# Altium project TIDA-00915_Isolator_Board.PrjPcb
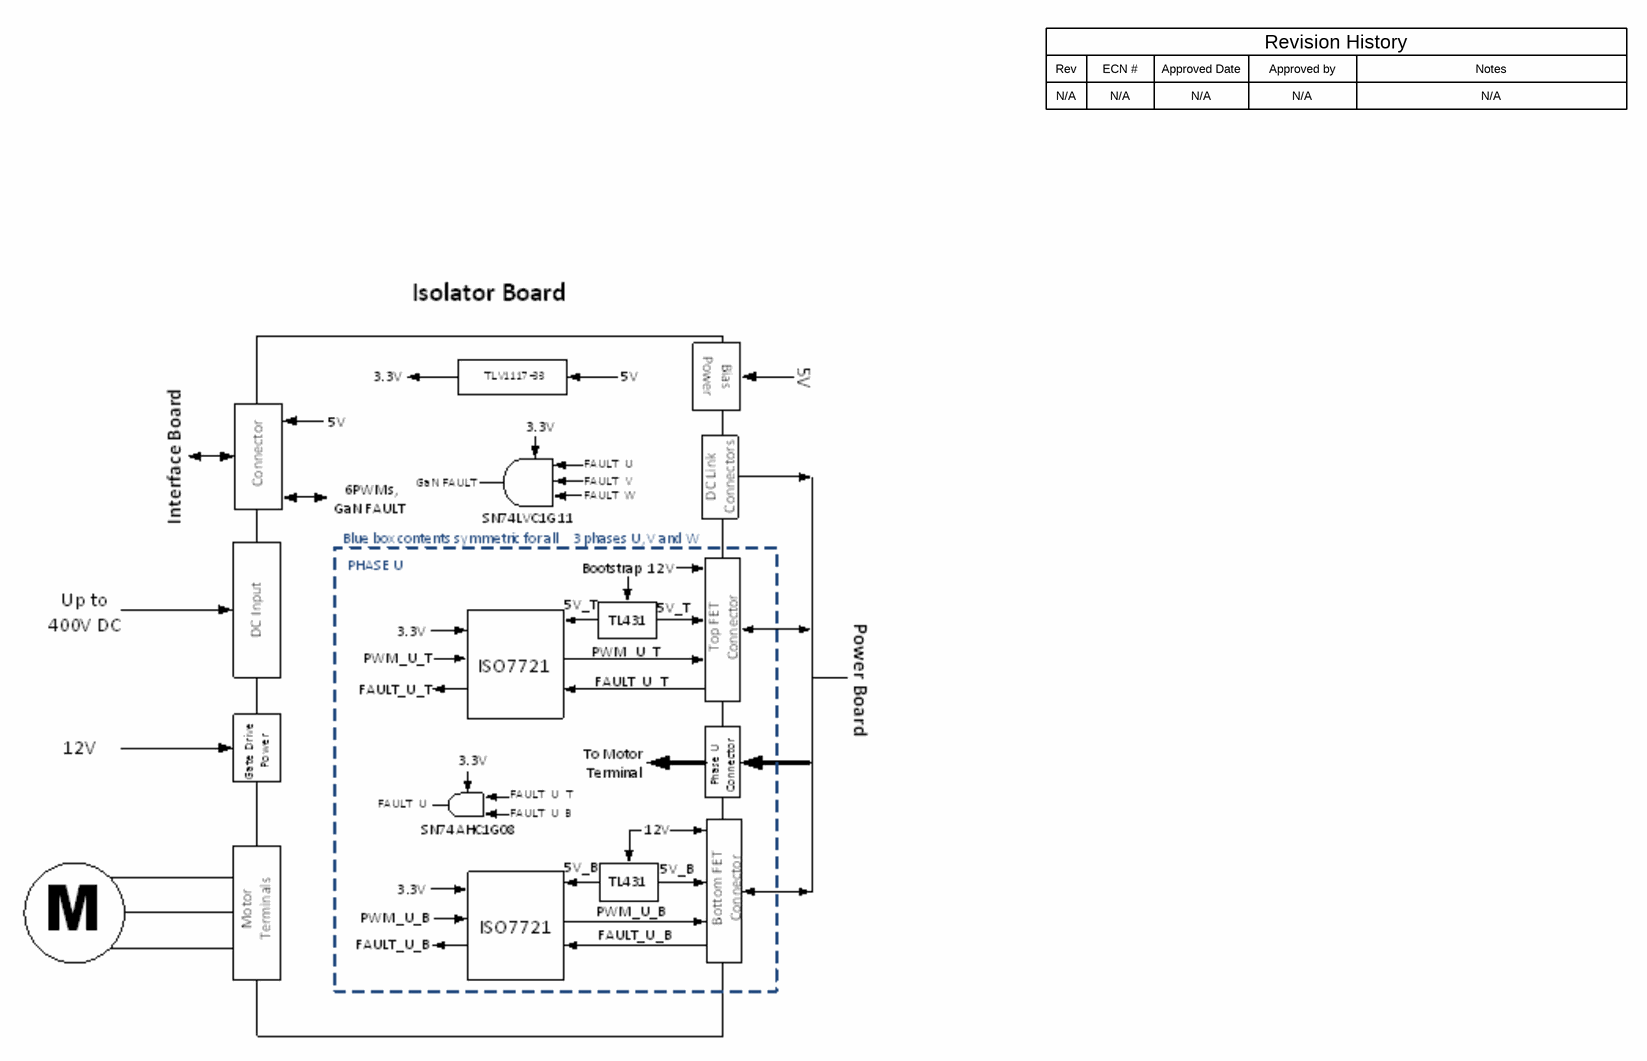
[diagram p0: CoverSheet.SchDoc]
TID: 00915; TechSupport: http://www.ti.com/support; SCH_Rev: E1; PRJ_Title: TIDA-00915_Isolator_Board; PRJ_Number: TIDA-00915_Isolator_Board; PRJ_Customer: Public Release; PCB_Rev: E1; CopyrightYear: 2019
6 sheets, 132 parts. Net scope: global (net labels, ports and power ports of the same name join across sheets).
Board file: TIDA-00915_Isolator_Board.PcbDoc
Sheets:
  CoverSheet.SchDoc
  EVM_Hardware.SchDoc
  Phase_U.SchDoc
  Phase_V.SchDoc
  Phase_W.SchDoc
  MCU_Interface.SchDoc

## Sheet CoverSheet.SchDoc
size 431 x 279 mm; Date: Not shown in title block; ApprovedBy: Not shown in title block; CheckedBy: Not shown in title block; Author: Not shown in title block; CompanyName: Not shown in title block; Engineer: Not shown in title block; Organization: Not shown in title block; Address1: Not shown in title block; Address2: Not shown in title block; Address3: Not shown in title block; Address4: Not shown in title block; DocumentNumber: 1; Revision: Use project parameter SCH_Rev; SheetNumber: 1; SheetTotal: 3; PageSetup: Record=PageOptions¦CenterHorizontal=True¦CenterVertical=True¦PrintScale=1.00¦XCorrection=1.00¦YCorrection=1.00¦PrintKind=0¦BorderSize=5000000¦LeftOffset=0¦BottomOffset=0¦Orientation=2¦PaperLength=1000¦PaperWidth=1000¦Scale=100¦PaperSource=15¦PrintQuality=600¦MediaType=1¦DitherType=10¦PaperKind=Letter¦PrintScaleMode=1

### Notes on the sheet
- Rev
- N/A
- ECN #
- Approved Date
- Approved by
- Revision History
- Notes

## Sheet EVM_Hardware.SchDoc
size 431 x 279 mm; Date: Not shown in title block; ApprovedBy: Not shown in title block; CheckedBy: Not shown in title block; Author: Not shown in title block; CompanyName: Not shown in title block; Engineer: Not shown in title block; Organization: Not shown in title block; Address1: Not shown in title block; Address2: Not shown in title block; Address3: Not shown in title block; Address4: Not shown in title block; DocumentNumber: 1; Revision: Use project parameter SCH_Rev; SheetNumber: 3; SheetTotal: 3; PageSetup: Record=PageOptions¦CenterHorizontal=True¦CenterVertical=True¦PrintScale=1.00¦XCorrection=1.00¦YCorrection=1.00¦PrintKind=0¦BorderSize=5000000¦LeftOffset=0¦BottomOffset=0¦Orientation=2¦PaperLength=1000¦PaperWidth=1000¦Scale=100¦PaperSource=15¦PrintQuality=600¦MediaType=1¦DitherType=10¦PaperKind=Letter¦PrintScaleMode=1
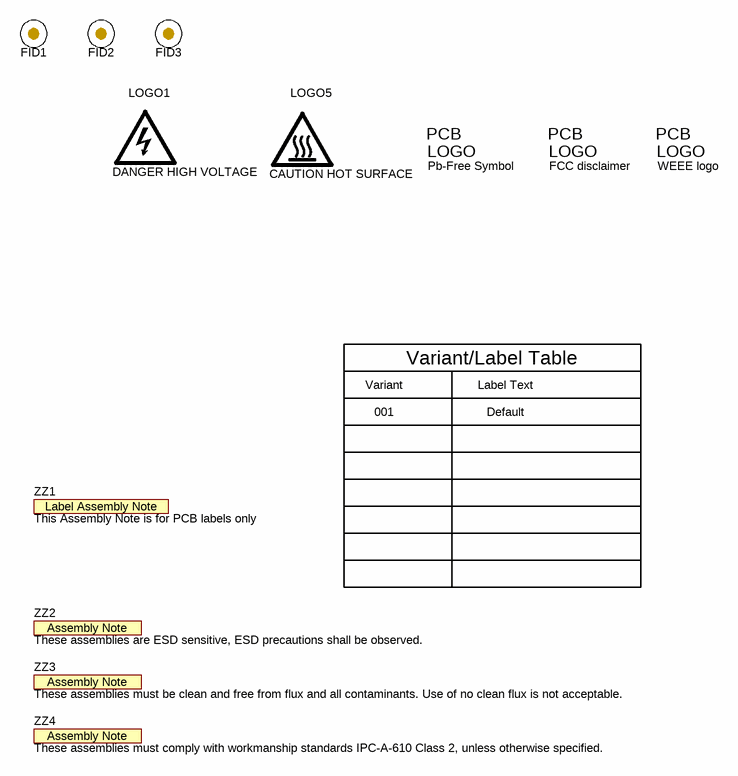
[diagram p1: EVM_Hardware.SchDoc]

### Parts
FID1  Fiducial  [Fiducial10-20]  (value not drawn)
FID2  Fiducial  [Fiducial10-20]  (value not drawn)
FID3  Fiducial  [Fiducial10-20]  (value not drawn)
LOGO1  DANGER HIGH VOLTAGE  [IEC_HighVoltage_Small]  (no BOM)
Logo2  Pb-Free Symbol  [Pb-Free_Overlay_Small]  (no BOM)
Logo3  FCC disclaimer  [FCC_disclaimer]  (no BOM)
Logo4  WEEE logo  [WEEE_Minimum]  (no BOM)
LOGO5  CAUTION HOT SURFACE  [IEC_HotSurface_Small]  (no BOM)
ZZ1  This Assembly Note is for PCB labels only  [AssemblyNoteLabel]  (no BOM)
ZZ2  These assemblies are ESD sensitive, ESD precautions shall be observed.  [AssemblyNote]  (no BOM)
ZZ3  These assemblies must be clean and free from flux and all contaminants. Use of no clean flux is not acceptable.  [AssemblyNote]  (no BOM)
ZZ4  These assemblies must comply with workmanship standards IPC-A-610 Class 2, unless otherwise specified.  [AssemblyNote]  (no BOM)

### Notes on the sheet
- Variant
- Variant/Label Table
- Label Text
- 001
- Default

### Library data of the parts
FID1-FID3 = CMP-0077181-1: Fiducial mark.  There is nothing to buy or mount.
LOGO1 = CMP-0074835-1: IEC 61010-1 High Voltage Warning; Library Reference: IEC_HighVoltage; SymbolCreator: a0412235
Logo2 = CMP-0074839-1: SymbolCreator: a0412235; Library Reference: Logo
Logo3 = CMP-0074847-1: FCC_disclaimer; Library Reference: Logo
Logo4 = CMP-0074769-1
LOGO5 = CMP-0074837-1: IEC 61010-1 Hot Surface Warning; Library Reference: IEC_HotSurface; SymbolCreator: a0412235
ZZ1 = CMP-0003616-3
ZZ2 = CMP-0077236-1
ZZ3 = CMP-0077237-1
ZZ4 = CMP-0077238-1

## Sheet Phase_U.SchDoc
size 431 x 279 mm; Date: Not shown in title block; ApprovedBy: Not shown in title block; CheckedBy: Not shown in title block; Author: Not shown in title block; CompanyName: Not shown in title block; Engineer: Not shown in title block; Organization: Not shown in title block; Address1: Not shown in title block; Address2: Not shown in title block; Address3: Not shown in title block; Address4: Not shown in title block; DocumentNumber: 1; Revision: Use project parameter SCH_Rev; SheetNumber: 2; SheetTotal: 3; PageSetup: Record=PageOptions¦CenterHorizontal=True¦CenterVertical=True¦PrintScale=1.00¦XCorrection=1.00¦YCorrection=1.00¦PrintKind=0¦BorderSize=5000000¦LeftOffset=0¦BottomOffset=0¦Orientation=2¦PaperLength=1000¦PaperWidth=1000¦Scale=100¦PaperSource=15¦PrintQuality=600¦MediaType=1¦DitherType=10¦PaperKind=Letter¦PrintScaleMode=1
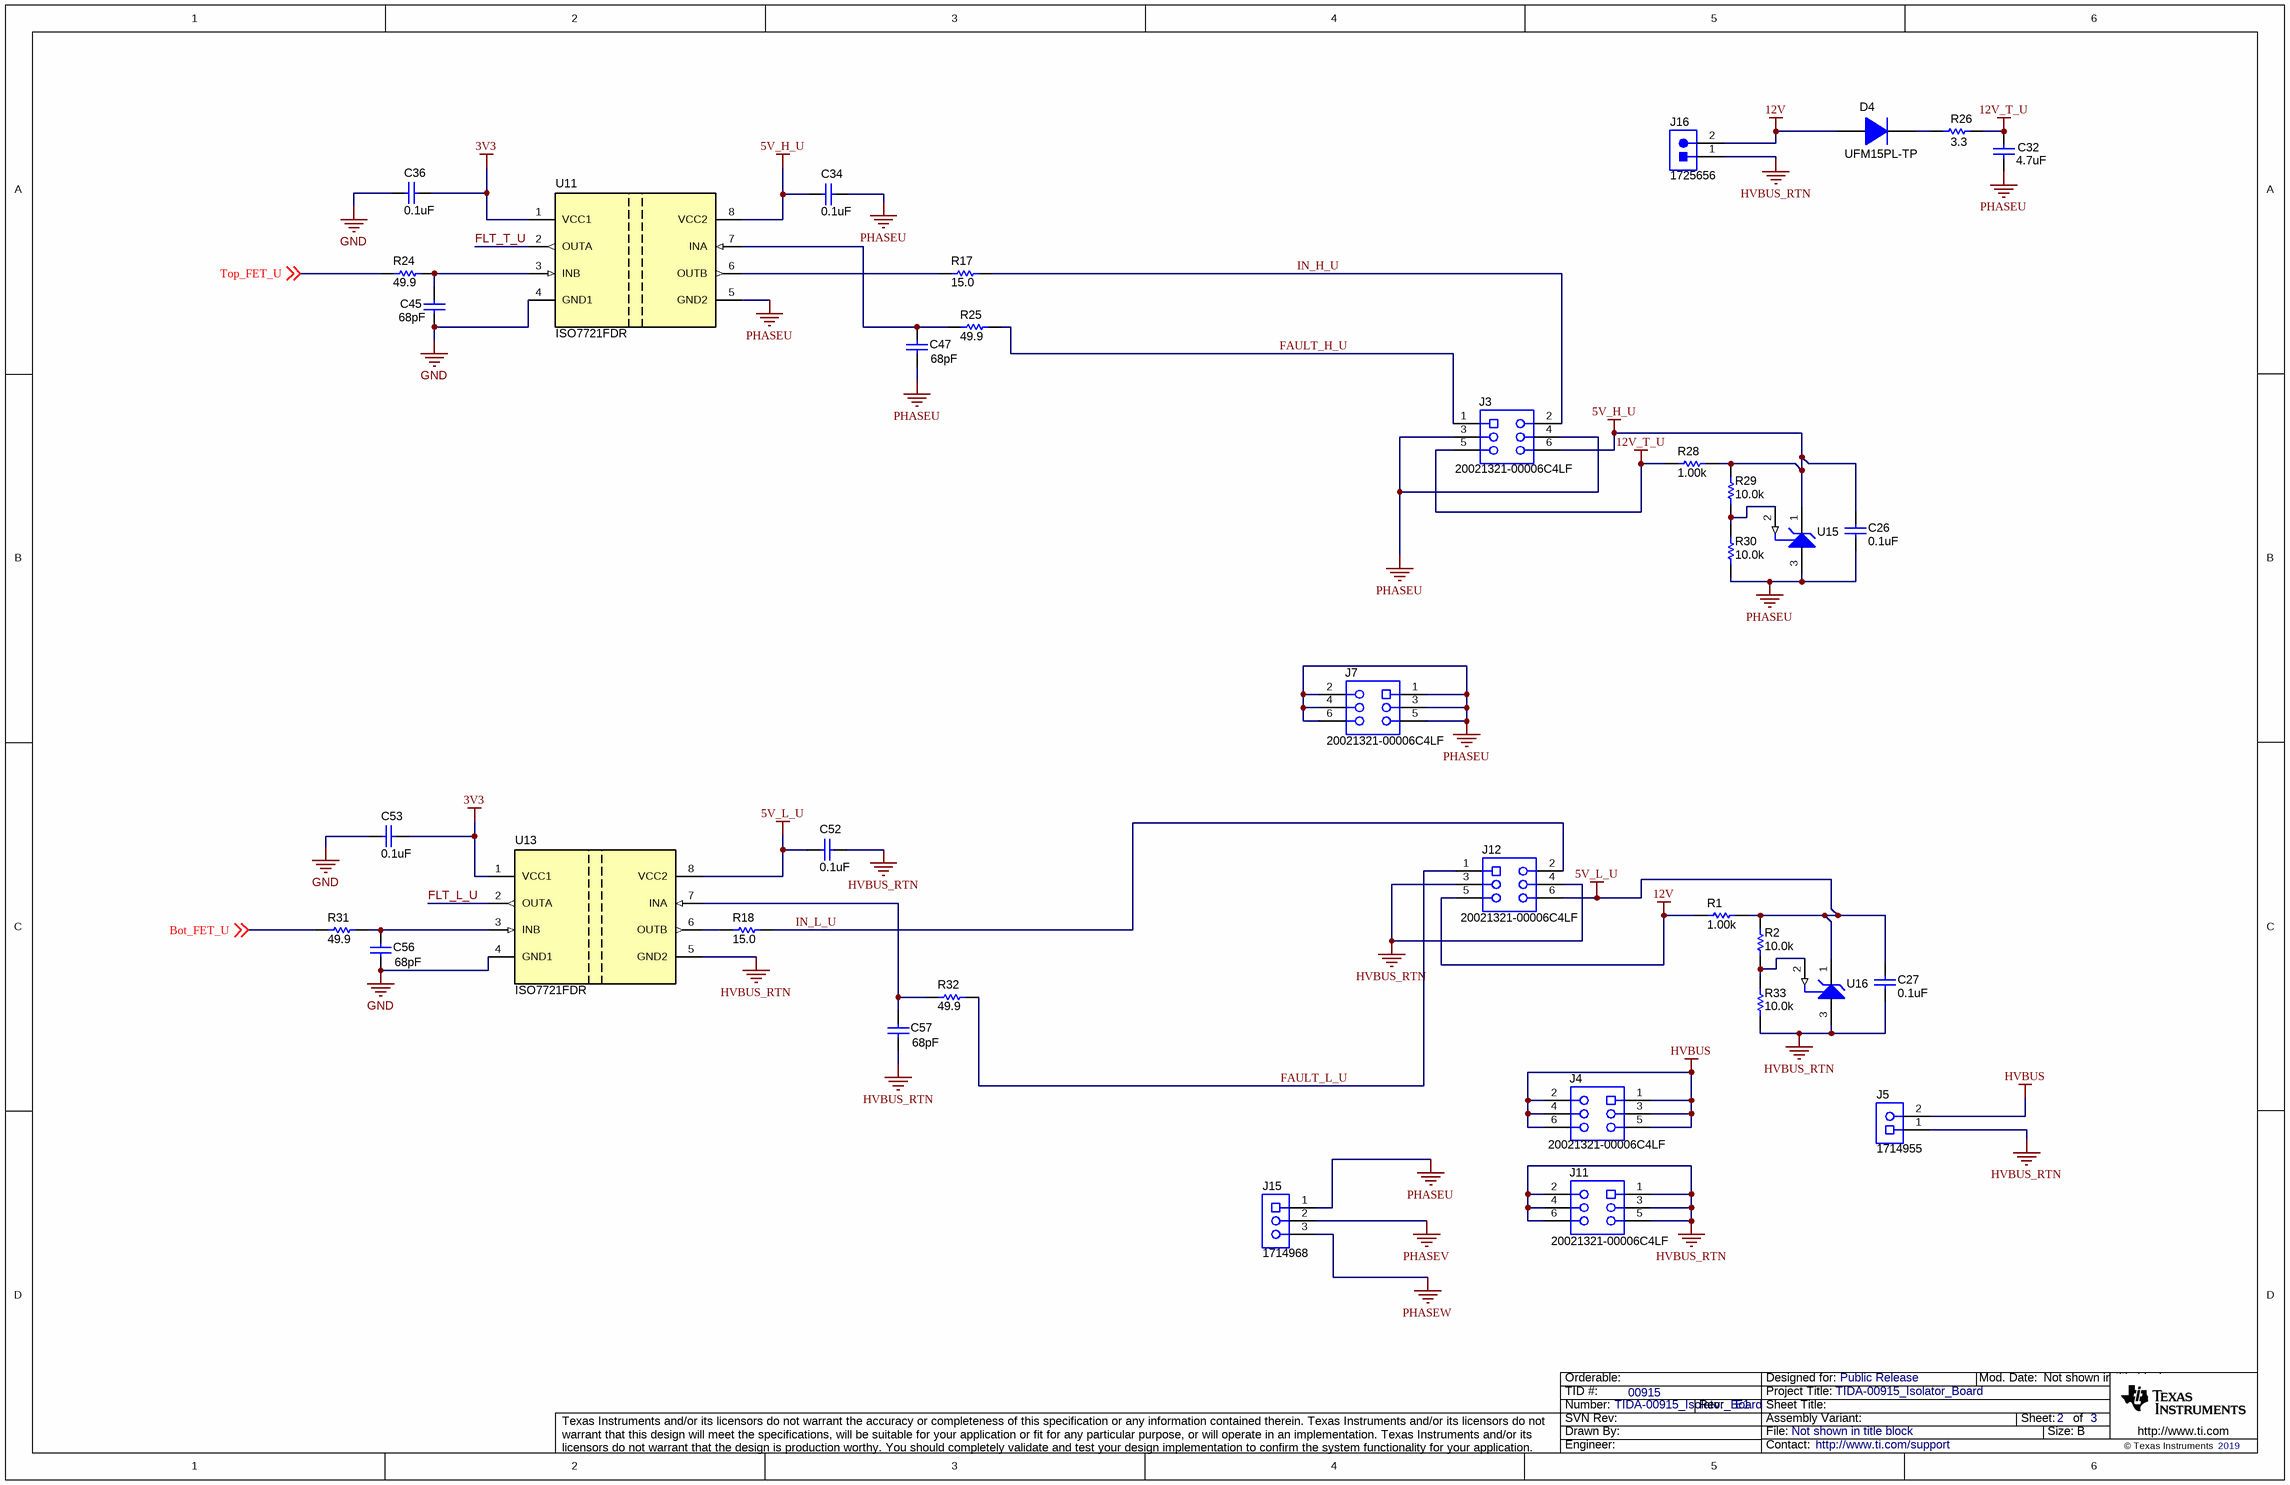
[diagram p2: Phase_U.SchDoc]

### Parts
C26  ValueDisplayed: 0.1uF  [0603]  (hidden comment: 06035C104KAT2A)
C27  ValueDisplayed: 0.1uF  [0603]  (hidden comment: 06035C104KAT2A)
C32  ValueDisplayed: 4.7uF  [0805_HV]  (hidden comment: C2012X7R1V475K125AC)
C34  ValueDisplayed: 0.1uF  [0603]  (hidden comment: 06035C104KAT2A)
C36  ValueDisplayed: 0.1uF  [0603]  (hidden comment: 06035C104KAT2A)
C45  ValueDisplayed: 68pF  [0402]  (hidden comment: C1005C0G1H680J050BA)
C47  ValueDisplayed: 68pF  [0402]  (hidden comment: C1005C0G1H680J050BA)
C52  ValueDisplayed: 0.1uF  [0603]  (hidden comment: 06035C104KAT2A)
C53  ValueDisplayed: 0.1uF  [0603]  (hidden comment: 06035C104KAT2A)
C56  ValueDisplayed: 68pF  [0402]  (hidden comment: C1005C0G1H680J050BA)
C57  ValueDisplayed: 68pF  [0402]  (hidden comment: C1005C0G1H680J050BA)
D4  UFM15PL-TP  [SOD-123FL]
J3  20021321-00006C4LF  [FCI_20021321-00006XXLF]
J4  20021321-00006C4LF  [FCI_20021321-00006XXLF]
J5  1714955  [Phoenix_1714955]
J7  20021321-00006C4LF  [FCI_20021321-00006XXLF]
J11  20021321-00006C4LF  [FCI_20021321-00006XXLF]
J12  20021321-00006C4LF  [FCI_20021321-00006XXLF]
J15  1714968  [Phoenix_1714968]
J16  1725656  [CONN_1725656_1]
R1  ValueDisplayed: 1.00k  [0603]  (hidden comment: RC0603FR-071KL)
R2  ValueDisplayed: 10.0k  [0402]  (hidden comment: RC0402FR-0710KL)
R17  ValueDisplayed: 15.0  [0603]  (hidden comment: RC0603FR-0715RL)
R18  ValueDisplayed: 15.0  [0603]  (hidden comment: RC0603FR-0715RL)
R24  ValueDisplayed: 49.9  [0603]  (hidden comment: RC0603FR-0749R9L)
R25  ValueDisplayed: 49.9  [0603]  (hidden comment: RC0603FR-0749R9L)
R26  ValueDisplayed: 3.3  [0603]  (hidden comment: CRCW06033R30JNEA)
R28  ValueDisplayed: 1.00k  [0603]  (hidden comment: RC0603FR-071KL)
R29  ValueDisplayed: 10.0k  [0402]  (hidden comment: RC0402FR-0710KL)
R30  ValueDisplayed: 10.0k  [0402]  (hidden comment: RC0402FR-0710KL)
R31  ValueDisplayed: 49.9  [0603]  (hidden comment: RC0603FR-0749R9L)
R32  ValueDisplayed: 49.9  [0603]  (hidden comment: RC0603FR-0749R9L)
R33  ValueDisplayed: 10.0k  [0402]  (hidden comment: RC0402FR-0710KL)
U11  ISO7721FDR  [D0008B_HV]
U13  ISO7721FDR  [D0008B_HV]
U15  TL431ACDBZT  [DBZ0003A_N]  (value not drawn)
U16  TL431ACDBZT  [DBZ0003A_N]  (value not drawn)

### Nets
3V3: C36.2 C53.2 U11.1(VCC1) U13.1(VCC1)
5V_H_U: C26.1 C34.1 J3.6 R28.2 R29.2 U11.8(VCC2) U15.1(CATHODE)
5V_L_U: C27.1 C52.1 J12.6 R1.2 R2.2 U13.8(VCC2) U16.1(CATHODE)
12V: D4.2(A) J12.5 J16.2 R1.1
12V_T_U: C32.1 J3.5 R26.2 R28.1
GND: C36.1 C45.2 C53.1 C56.2 U11.4(GND1) U13.4(GND1)
HVBUS: J4.1 J4.2 J4.3 J4.4 J4.5 J4.6 J5.2
HVBUS_RTN: C27.2 C52.2 C57.2 J5.1 J11.1 J11.2 J11.3 J11.4 J11.5 J11.6 J12.3 J12.4 J16.1 R33.1 U13.5(GND2) U16.3(ANODE)
PHASEU: C26.2 C32.2 C34.2 C47.2 J3.3 J3.4 J7.1 J7.2 J7.3 J7.4 J7.5 J7.6 J15.1 R30.1 U11.5(GND2) U15.3(ANODE)
PHASEV: J15.2
PHASEW: J15.3
Bot_FET_U: R31.1 ; off-sheet Bot_FET_U
FAULT_H_U: J3.1 R25.2
FAULT_L_U: J12.1 R32.2
FLT_L_U: U13.2(OUTA)
FLT_T_U: U11.2(OUTA)
IN_H_U: J3.2 R17.2
IN_L_U: J12.2 R18.2
Top_FET_U: R24.1 ; off-sheet Top_FET_U
NetC45_1: C45.1 R24.2 U11.3(INB)
NetC47_1: C47.1 R25.1 U11.7(INA)
NetC56_1: C56.1 R31.2 U13.3(INB)
NetC57_1: C57.1 R32.1 U13.7(INA)
NetD4_1: D4.1(K) R26.1
NetR2_1: R2.1 R33.2 U16.2(REF)
NetR17_1: R17.1 U11.6(OUTB)
NetR18_1: R18.1 U13.6(OUTB)
NetR29_1: R29.1 R30.2 U15.2(REF)

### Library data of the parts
C26 C27 C34 C36 C52 C53 = CMP-0006802-4: CAP, CERM, 0.1 uF, 50 V, +/- 10%, X7R, 0603; Manufacturer: AVX; TaMin_C: -55°C; Polarized: N; SizeAreaWB_mm2: 4.68; Value1: Unknown; U/M: EA; Value: 0.1uF; TaMax_C: 125°C; SizeZ_mm: 1; SizeX_mm: 1.6; SizeY_mm: 0.8; Value2: 50V; SizeArea_mm2: 1.28; CompType: Capacitor; Cap_F: 100nF; AEC Category: Q200
C32 = CMP-0007885-2: CAP, CERM, 4.7 uF, 35 V, +/- 10%, X7R, 0805; Manufacturer: TDK; TaMin_C: -55°C; ESR_ohm: 2.346m; Polarized: N; SizeAreaWB_mm2: 6.75; Value1: 0.002346 ohm; U/M: EA; Value: 4.7uF; TaMax_C: 125°C; SizeZ_mm: 1.45; SizeX_mm: 2; SizeY_mm: 1.25; Cap_Case: 0805; Value2: 35V; SizeArea_mm2: 2.5; CompType: Capacitor; Cap_F: 4.7µF; IRMS_A: 4.26021A; AEC Category: Q200
C45 C47 C56 C57 = CMP-0006251-2: CAP, CERM, 68 pF, 50 V, +/- 5%, C0G/NP0, 0402; Manufacturer: TDK; TaMin_C: -55°C; Polarized: N; SizeAreaWB_mm2: 3; Value1: Unknown; U/M: EA; Value: 68pF; TaMax_C: 125°C; SizeZ_mm: 0.6; SizeX_mm: 1; SizeY_mm: 0.5; Value2: 50V; CompType: Capacitor; AEC Category: Q200
D4 = CMP-0029148-2: Diode, Ultrafast, 600 V, 1 A, SOD-123FL; Manufacturer: Micro Commercial Components; SizeY_mm: 1.65; Value: 600V; Io_A: 1A; Green_Lifecycle: Not Set; Green_REACh: Incomplete; SizeX_mm: 3.6; SizeAreaWB_mm2: 12.19; SizeArea_mm2: 5.94; AEC Qualified: N; Value2: 1.7V; SizeZ_mm: 0.98; AEC Category: Q101; TJmax_C: 150°C
J3 J4 J7 J11 J12 = CMP-0086011-1: Receptacle, 1.27mm, 3x2, Gold, SMT; Manufacturer: FCI; Row_Count: 2; Gender: Female; RowSpacing_mm: 1.27
J5 = CMP-0055505-1: Terminal Block, 2x1, 6.35mm, Green, TH; Manufacturer: Phoenix Contact; CNHeader: FALSE; Shrouded: Y; Gender: Female; Row_Count: 1; Pitch_mm: 6.35; CT: TRUE
J15 = CMP-0055483-1: Terminal Block, 3x1, 6.35 mm, TH; Manufacturer: Phoenix Contact; CT: TRUE; CNHeader: FALSE
J16 = CMP-0055479-2: Terminal Block, 100mil, 2x1, 6A, 63V, TH; Manufacturer: Phoenix Contact; Green_REACh: Incomplete; CNHeader: FALSE; CT: TRUE; Green_Lifecycle: Not Set
R1 R28 = CMP-0022895-5: RES, 1.00 k, 1%, 0.1 W, 0603; Manufacturer: Yageo; Power_W: 100mW; TempCo: 100 ppm/C; Value_Code: 1k00; Value: 1.00k; EIA_Code: E96; Res_ohm: 1k; SizeX_mm: 1.6; SizeY_mm: 0.8; SizeZ_mm: 1; Value2: 0.1W; SizeArea_mm2: 1.28; CompType: Resistor; AEC Qualified: N; VDC_V: 75V; AEC Category: Q200; SizeAreaWB_mm2: 4.68
R2 R33 = CMP-0078669-1: RES, 10.0 k, 1%, 0.063 W, 0402; Manufacturer: Yageo America; Power_W: 63mW; Green_Lifecycle: Active; TempCo: 100 ppm/C; Value_Code: 10k0; Green_REACh: Passed; Value: 10.0k; EIA_Code: E96; Res_ohm: 10k; SizeX_mm: 1; SizeY_mm: 0.5; SizeZ_mm: 0.6; Value2: 0.063W; CompType: Resistor; AEC Qualified: N; AEC Category: Q200
R17 R18 = CMP-0022819-4: RES, 15.0, 1%, 0.1 W, 0603; Manufacturer: Yageo; Power_W: 100mW; TempCo: 100 ppm/C; Value_Code: 15R0; Value: 15.0; EIA_Code: E96; Res_ohm: 15; SizeX_mm: 1.6; SizeY_mm: 0.8; SizeZ_mm: 1; Value2: 0.1W; SizeArea_mm2: 1.28; AEC Qualified: N; VDC_V: 75V; AEC Category: Q200; SizeAreaWB_mm2: 4.68
R24 R25 R31 R32 = CMP-0023143-5: RES, 49.9, 1%, 0.1 W, 0603; Manufacturer: Yageo; Power_W: 100mW; TempCo: 100 ppm/C; Value_Code: 49R9; Value: 49.9; EIA_Code: E96; SizeX_mm: 1.6; SizeY_mm: 0.8; SizeZ_mm: 1; Value2: 0.1W; SizeArea_mm2: 1.28; AEC Qualified: N; VDC_V: 75V; AEC Category: Q200; SizeAreaWB_mm2: 4.68
R26 = CMP-0025805-4: RES, 3.3, 5%, 0.1 W, AEC-Q200 Grade 0, 0603; Manufacturer: Vishay-Dale; Power_W: 100mW; TempCo: 200 ppm/C; Value_Code: 3R30; Value: 3.3; EIA_Code: E24; SizeX_mm: 1.6; SizeY_mm: 0.8; SizeZ_mm: 1; Value2: 0.1W; SizeArea_mm2: 1.28; CompType: Resistor; AEC Qualified: Y; VDC_V: 75V; AEC Category: Q200; AEC Grade: 0
R29 R30 = CMP-0078669-1: RES, 10.0 k, 1%, 0.063 W, 0402; Manufacturer: Yageo America; Power_W: 63mW; Green_Lifecycle: Active; TempCo: 100 ppm/C; Value_Code: 10k0; Green_REACh: Passed; Value: 10.0k; EIA_Code: E96; Res_ohm: 10k; SizeX_mm: 1; SizeY_mm: 0.5; SizeZ_mm: 0.6; Value2: 0.063W; AEC Qualified: N; AEC Category: Q200
U11 U13 = CMP-0085673-1: High Speed, Robust EMC Reinforced Dual-Channel Digital Isolator, D0008B (SOIC-8); Alternate Manufacturer: Texas Instruments; Rating: Catalog; SizeAreaWB_mm2: 55.2; SizeY_mm: 4.9; SizeZ_mm: 1.75; AEC Qualified: N; SizeX_mm: 6; CompType: IC; SizeArea_mm2: 29.4; AEC Category: Q200
U15 U16 = CMP-0033071-1: Adjustable Precision Shunt Regulator, 34 ppm / degC, 100 mA, 0 to 70 degC, 3-pin SOT-23 (DBZ), Green (RoHS & no Sb/Br); Manufacturer: Texas Instruments; VO Adj(Max)(V): 36; Iout/Iz(Max)(mA): 100; Min Iz for Regulation(uA): 600; Temp Coeff(Typ)(ppm/ degree C): 34; SubFamily: Shunt Voltage Reference; Initial Accuracy @ 25/deg C(%): 1; Temp Coeff(Max)(ppm/ degree C): 92; Rating: Catalog; VO Adj(Min)(V): 2.495

## Sheet Phase_V.SchDoc
size 431 x 279 mm; Date: Not shown in title block; ApprovedBy: Not shown in title block; CheckedBy: Not shown in title block; Author: Not shown in title block; CompanyName: Not shown in title block; Engineer: Not shown in title block; Organization: Not shown in title block; Address1: Not shown in title block; Address2: Not shown in title block; Address3: Not shown in title block; Address4: Not shown in title block; DocumentNumber: 1; Revision: Use project parameter SCH_Rev; SheetNumber: 2; SheetTotal: 3; PageSetup: Record=PageOptions¦CenterHorizontal=True¦CenterVertical=True¦PrintScale=1.00¦XCorrection=1.00¦YCorrection=1.00¦PrintKind=0¦BorderSize=5000000¦LeftOffset=0¦BottomOffset=0¦Orientation=2¦PaperLength=1000¦PaperWidth=1000¦Scale=100¦PaperSource=15¦PrintQuality=600¦MediaType=1¦DitherType=10¦PaperKind=Letter¦PrintScaleMode=1
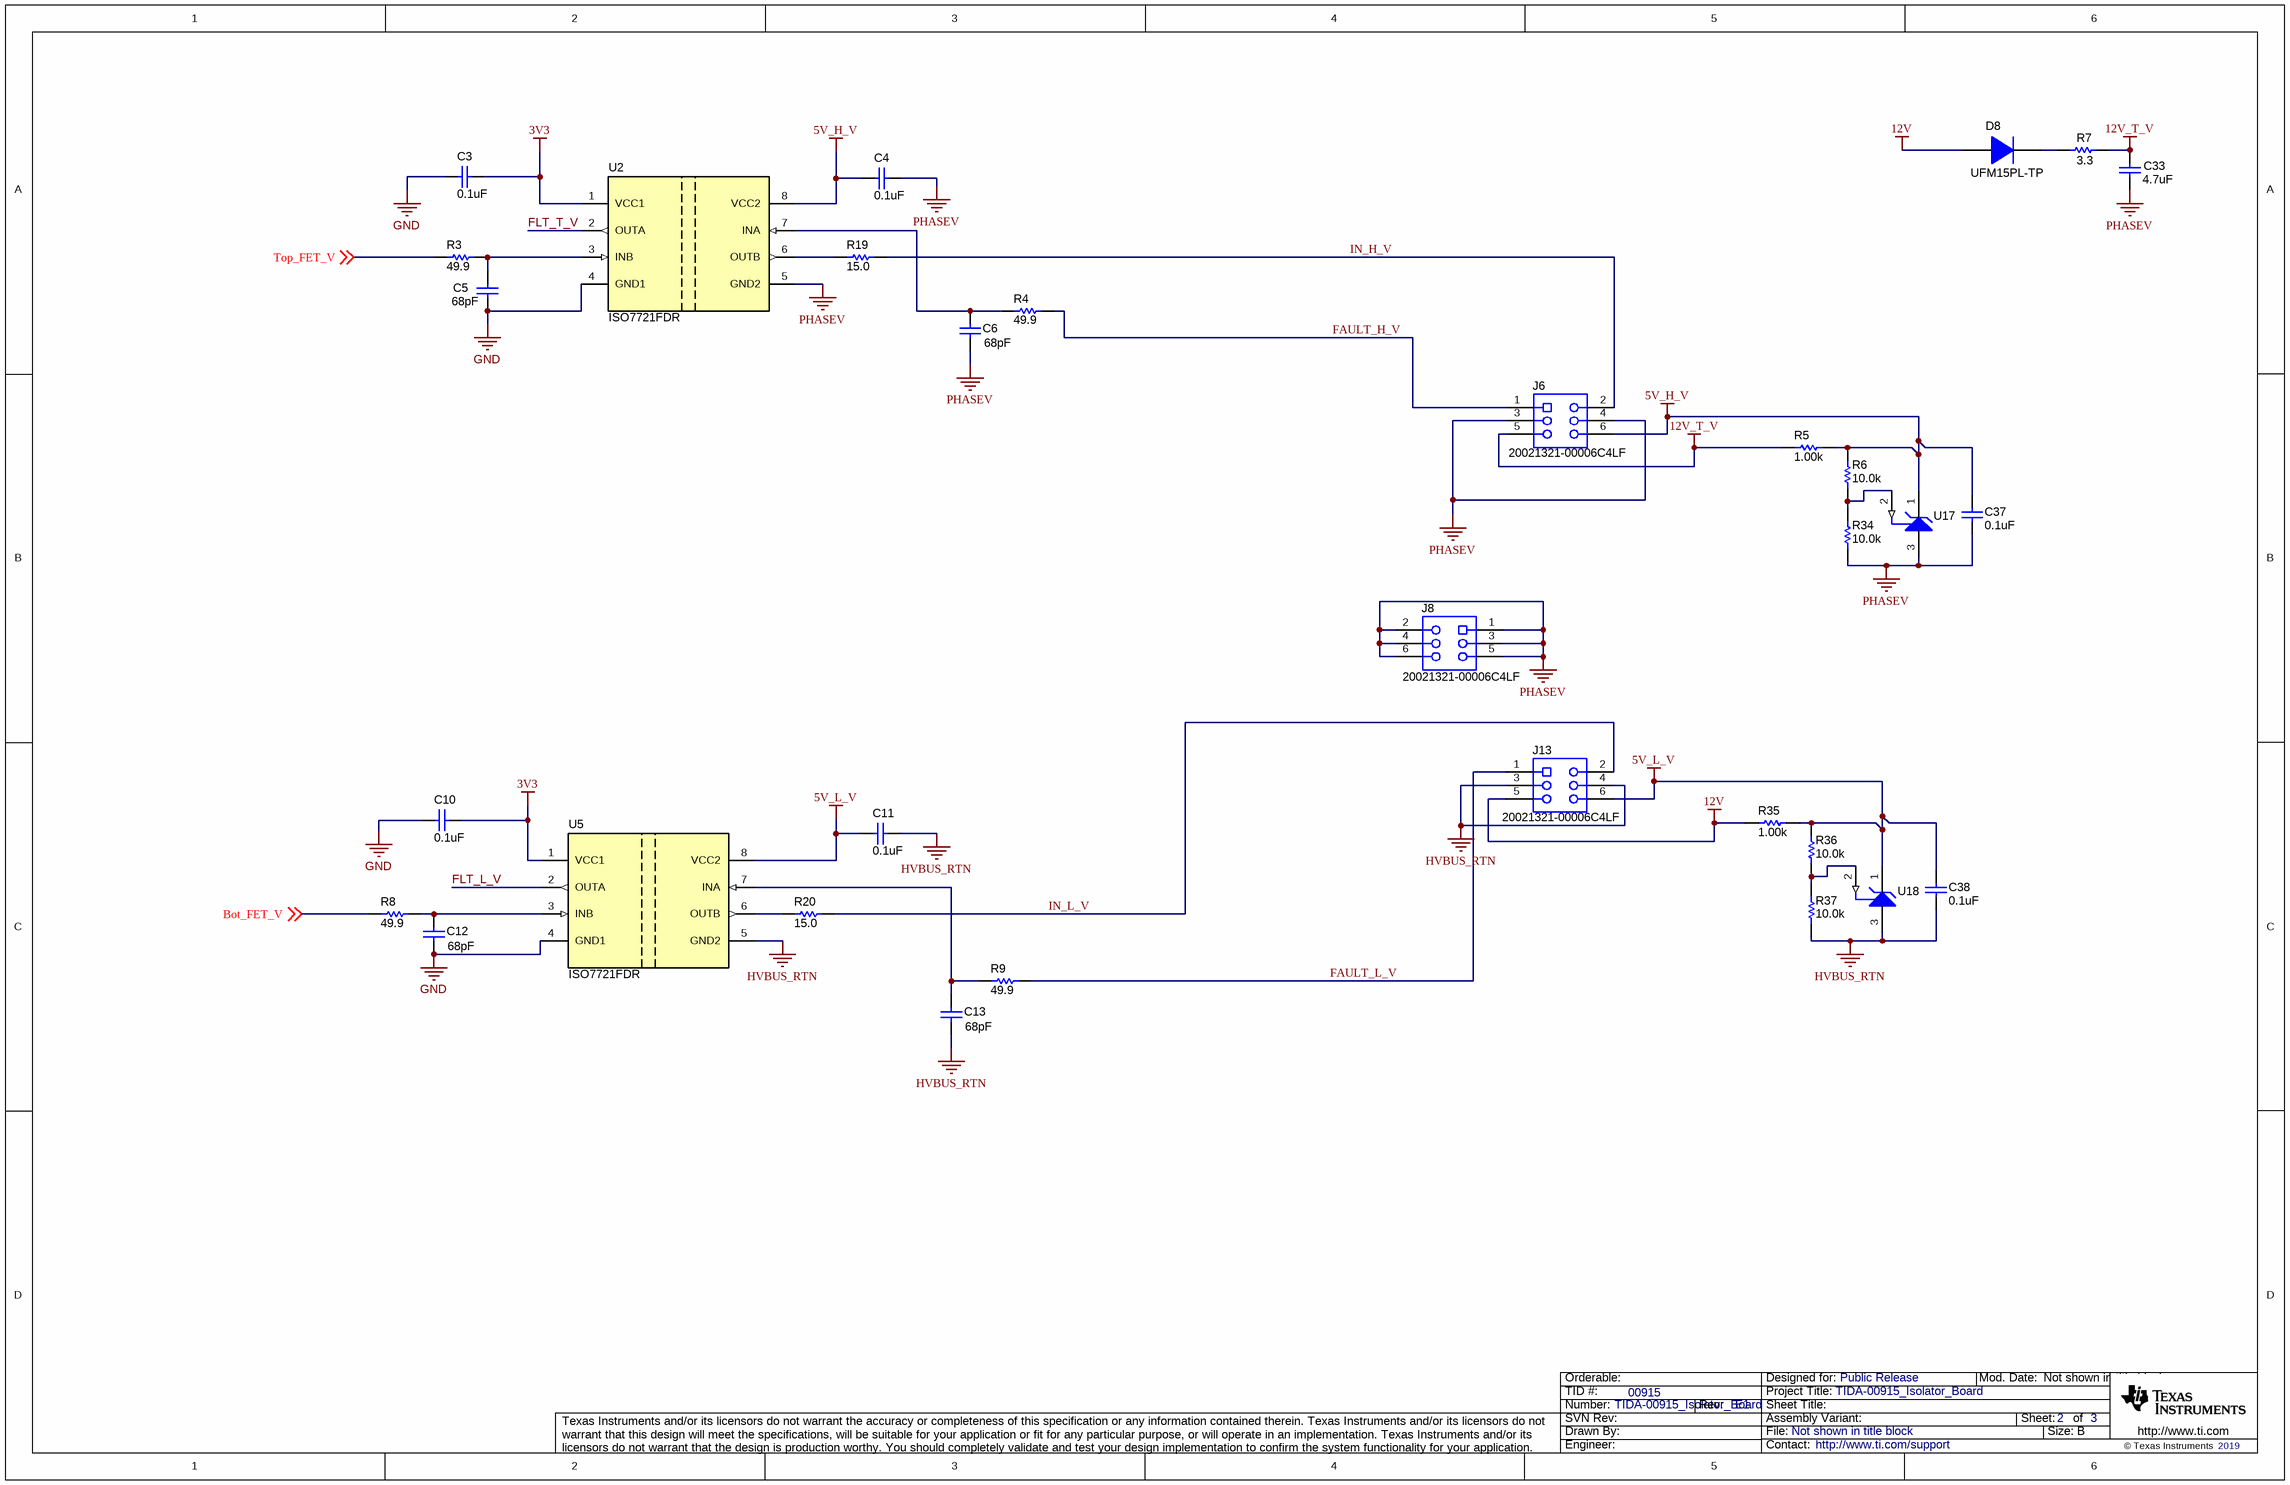
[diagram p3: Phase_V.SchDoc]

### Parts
C3  ValueDisplayed: 0.1uF  [0603]  (hidden comment: 06035C104KAT2A)
C4  ValueDisplayed: 0.1uF  [0603]  (hidden comment: 06035C104KAT2A)
C5  ValueDisplayed: 68pF  [0402]  (hidden comment: C1005C0G1H680J050BA)
C6  ValueDisplayed: 68pF  [0402]  (hidden comment: C1005C0G1H680J050BA)
C10  ValueDisplayed: 0.1uF  [0603]  (hidden comment: 06035C104KAT2A)
C11  ValueDisplayed: 0.1uF  [0603]  (hidden comment: 06035C104KAT2A)
C12  ValueDisplayed: 68pF  [0402]  (hidden comment: C1005C0G1H680J050BA)
C13  ValueDisplayed: 68pF  [0402]  (hidden comment: C1005C0G1H680J050BA)
C33  ValueDisplayed: 4.7uF  [0805_HV]  (hidden comment: C2012X7R1V475K125AC)
C37  ValueDisplayed: 0.1uF  [0603]  (hidden comment: 06035C104KAT2A)
C38  ValueDisplayed: 0.1uF  [0603]  (hidden comment: 06035C104KAT2A)
D8  UFM15PL-TP  [SOD-123FL]
J6  20021321-00006C4LF  [FCI_20021321-00006XXLF]
J8  20021321-00006C4LF  [FCI_20021321-00006XXLF]
J13  20021321-00006C4LF  [FCI_20021321-00006XXLF]
R3  ValueDisplayed: 49.9  [0603]  (hidden comment: RC0603FR-0749R9L)
R4  ValueDisplayed: 49.9  [0603]  (hidden comment: RC0603FR-0749R9L)
R5  ValueDisplayed: 1.00k  [0603]  (hidden comment: RC0603FR-071KL)
R6  ValueDisplayed: 10.0k  [0402]  (hidden comment: RC0402FR-0710KL)
R7  ValueDisplayed: 3.3  [0603]  (hidden comment: CRCW06033R30JNEA)
R8  ValueDisplayed: 49.9  [0603]  (hidden comment: RC0603FR-0749R9L)
R9  ValueDisplayed: 49.9  [0603]  (hidden comment: RC0603FR-0749R9L)
R19  ValueDisplayed: 15.0  [0603]  (hidden comment: RC0603FR-0715RL)
R20  ValueDisplayed: 15.0  [0603]  (hidden comment: RC0603FR-0715RL)
R34  ValueDisplayed: 10.0k  [0402]  (hidden comment: RC0402FR-0710KL)
R35  ValueDisplayed: 1.00k  [0603]  (hidden comment: RC0603FR-071KL)
R36  ValueDisplayed: 10.0k  [0402]  (hidden comment: RC0402FR-0710KL)
R37  ValueDisplayed: 10.0k  [0402]  (hidden comment: RC0402FR-0710KL)
U2  ISO7721FDR  [D0008B_HV]
U5  ISO7721FDR  [D0008B_HV]
U17  TL431ACDBZT  [DBZ0003A_N]  (value not drawn)
U18  TL431ACDBZT  [DBZ0003A_N]  (value not drawn)

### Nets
3V3: C3.2 C10.2 U2.1(VCC1) U5.1(VCC1)
5V_H_V: C4.1 C37.1 J6.6 R5.2 R6.2 U2.8(VCC2) U17.1(CATHODE)
5V_L_V: C11.1 C38.1 J13.6 R35.2 R36.2 U5.8(VCC2) U18.1(CATHODE)
12V: D8.2(A) J13.5 R35.1
12V_T_V: C33.1 J6.5 R5.1 R7.2
GND: C3.1 C5.2 C10.1 C12.2 U2.4(GND1) U5.4(GND1)
HVBUS_RTN: C11.2 C13.2 C38.2 J13.3 J13.4 R37.1 U5.5(GND2) U18.3(ANODE)
PHASEV: C4.2 C6.2 C33.2 C37.2 J6.3 J6.4 J8.1 J8.2 J8.3 J8.4 J8.5 J8.6 R34.1 U2.5(GND2) U17.3(ANODE)
Bot_FET_V: R8.1 ; off-sheet Bot_FET_V
FAULT_H_V: J6.1 R4.2
FAULT_L_V: J13.1 R9.2
FLT_L_V: U5.2(OUTA)
FLT_T_V: U2.2(OUTA)
IN_H_V: J6.2 R19.2
IN_L_V: J13.2 R20.2
Top_FET_V: R3.1 ; off-sheet Top_FET_V
NetC5_1: C5.1 R3.2 U2.3(INB)
NetC6_1: C6.1 R4.1 U2.7(INA)
NetC12_1: C12.1 R8.2 U5.3(INB)
NetC13_1: C13.1 R9.1 U5.7(INA)
NetD8_1: D8.1(K) R7.1
NetR6_1: R6.1 R34.2 U17.2(REF)
NetR19_1: R19.1 U2.6(OUTB)
NetR20_1: R20.1 U5.6(OUTB)
NetR36_1: R36.1 R37.2 U18.2(REF)

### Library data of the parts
C3 C4 C10 C11 C37 C38 = CMP-0006802-4: as C26 on sheet Phase_U
C5 C6 C12 C13 = CMP-0006251-2: as C45 on sheet Phase_U
C33 = CMP-0007885-2: as C32 on sheet Phase_U
D8 = CMP-0029148-2: as D4 on sheet Phase_U
J6 J8 J13 = CMP-0086011-1: as J3 on sheet Phase_U
R3 R4 R8 R9 = CMP-0023143-5: as R24 on sheet Phase_U
R5 R35 = CMP-0022895-5: as R1 on sheet Phase_U
R6 R34 R36 R37 = CMP-0078669-1: as R2 on sheet Phase_U
R7 = CMP-0025805-4: RES, 3.3, 5%, 0.1 W, AEC-Q200 Grade 0, 0603; Manufacturer: Vishay-Dale; Power_W: 100mW; TempCo: 200 ppm/C; Value_Code: 3R30; Value: 3.3; EIA_Code: E24; SizeX_mm: 1.6; SizeY_mm: 0.8; SizeZ_mm: 1; Value2: 0.1W; SizeArea_mm2: 1.28; AEC Qualified: Y; VDC_V: 75V; AEC Category: Q200; AEC Grade: 0
R19 R20 = CMP-0022819-4: as R17 on sheet Phase_U
U2 U5 = CMP-0085673-1: as U11 on sheet Phase_U
U17 U18 = CMP-0033071-1: as U15 on sheet Phase_U

## Sheet Phase_W.SchDoc
size 431 x 279 mm; Date: Not shown in title block; ApprovedBy: Not shown in title block; CheckedBy: Not shown in title block; Author: Not shown in title block; CompanyName: Not shown in title block; Engineer: Not shown in title block; Organization: Not shown in title block; Address1: Not shown in title block; Address2: Not shown in title block; Address3: Not shown in title block; Address4: Not shown in title block; DocumentNumber: 1; Revision: Use project parameter SCH_Rev; SheetNumber: 2; SheetTotal: 3; PageSetup: Record=PageOptions¦CenterHorizontal=True¦CenterVertical=True¦PrintScale=1.00¦XCorrection=1.00¦YCorrection=1.00¦PrintKind=0¦BorderSize=5000000¦LeftOffset=0¦BottomOffset=0¦Orientation=2¦PaperLength=1000¦PaperWidth=1000¦Scale=100¦PaperSource=15¦PrintQuality=600¦MediaType=1¦DitherType=10¦PaperKind=Letter¦PrintScaleMode=1
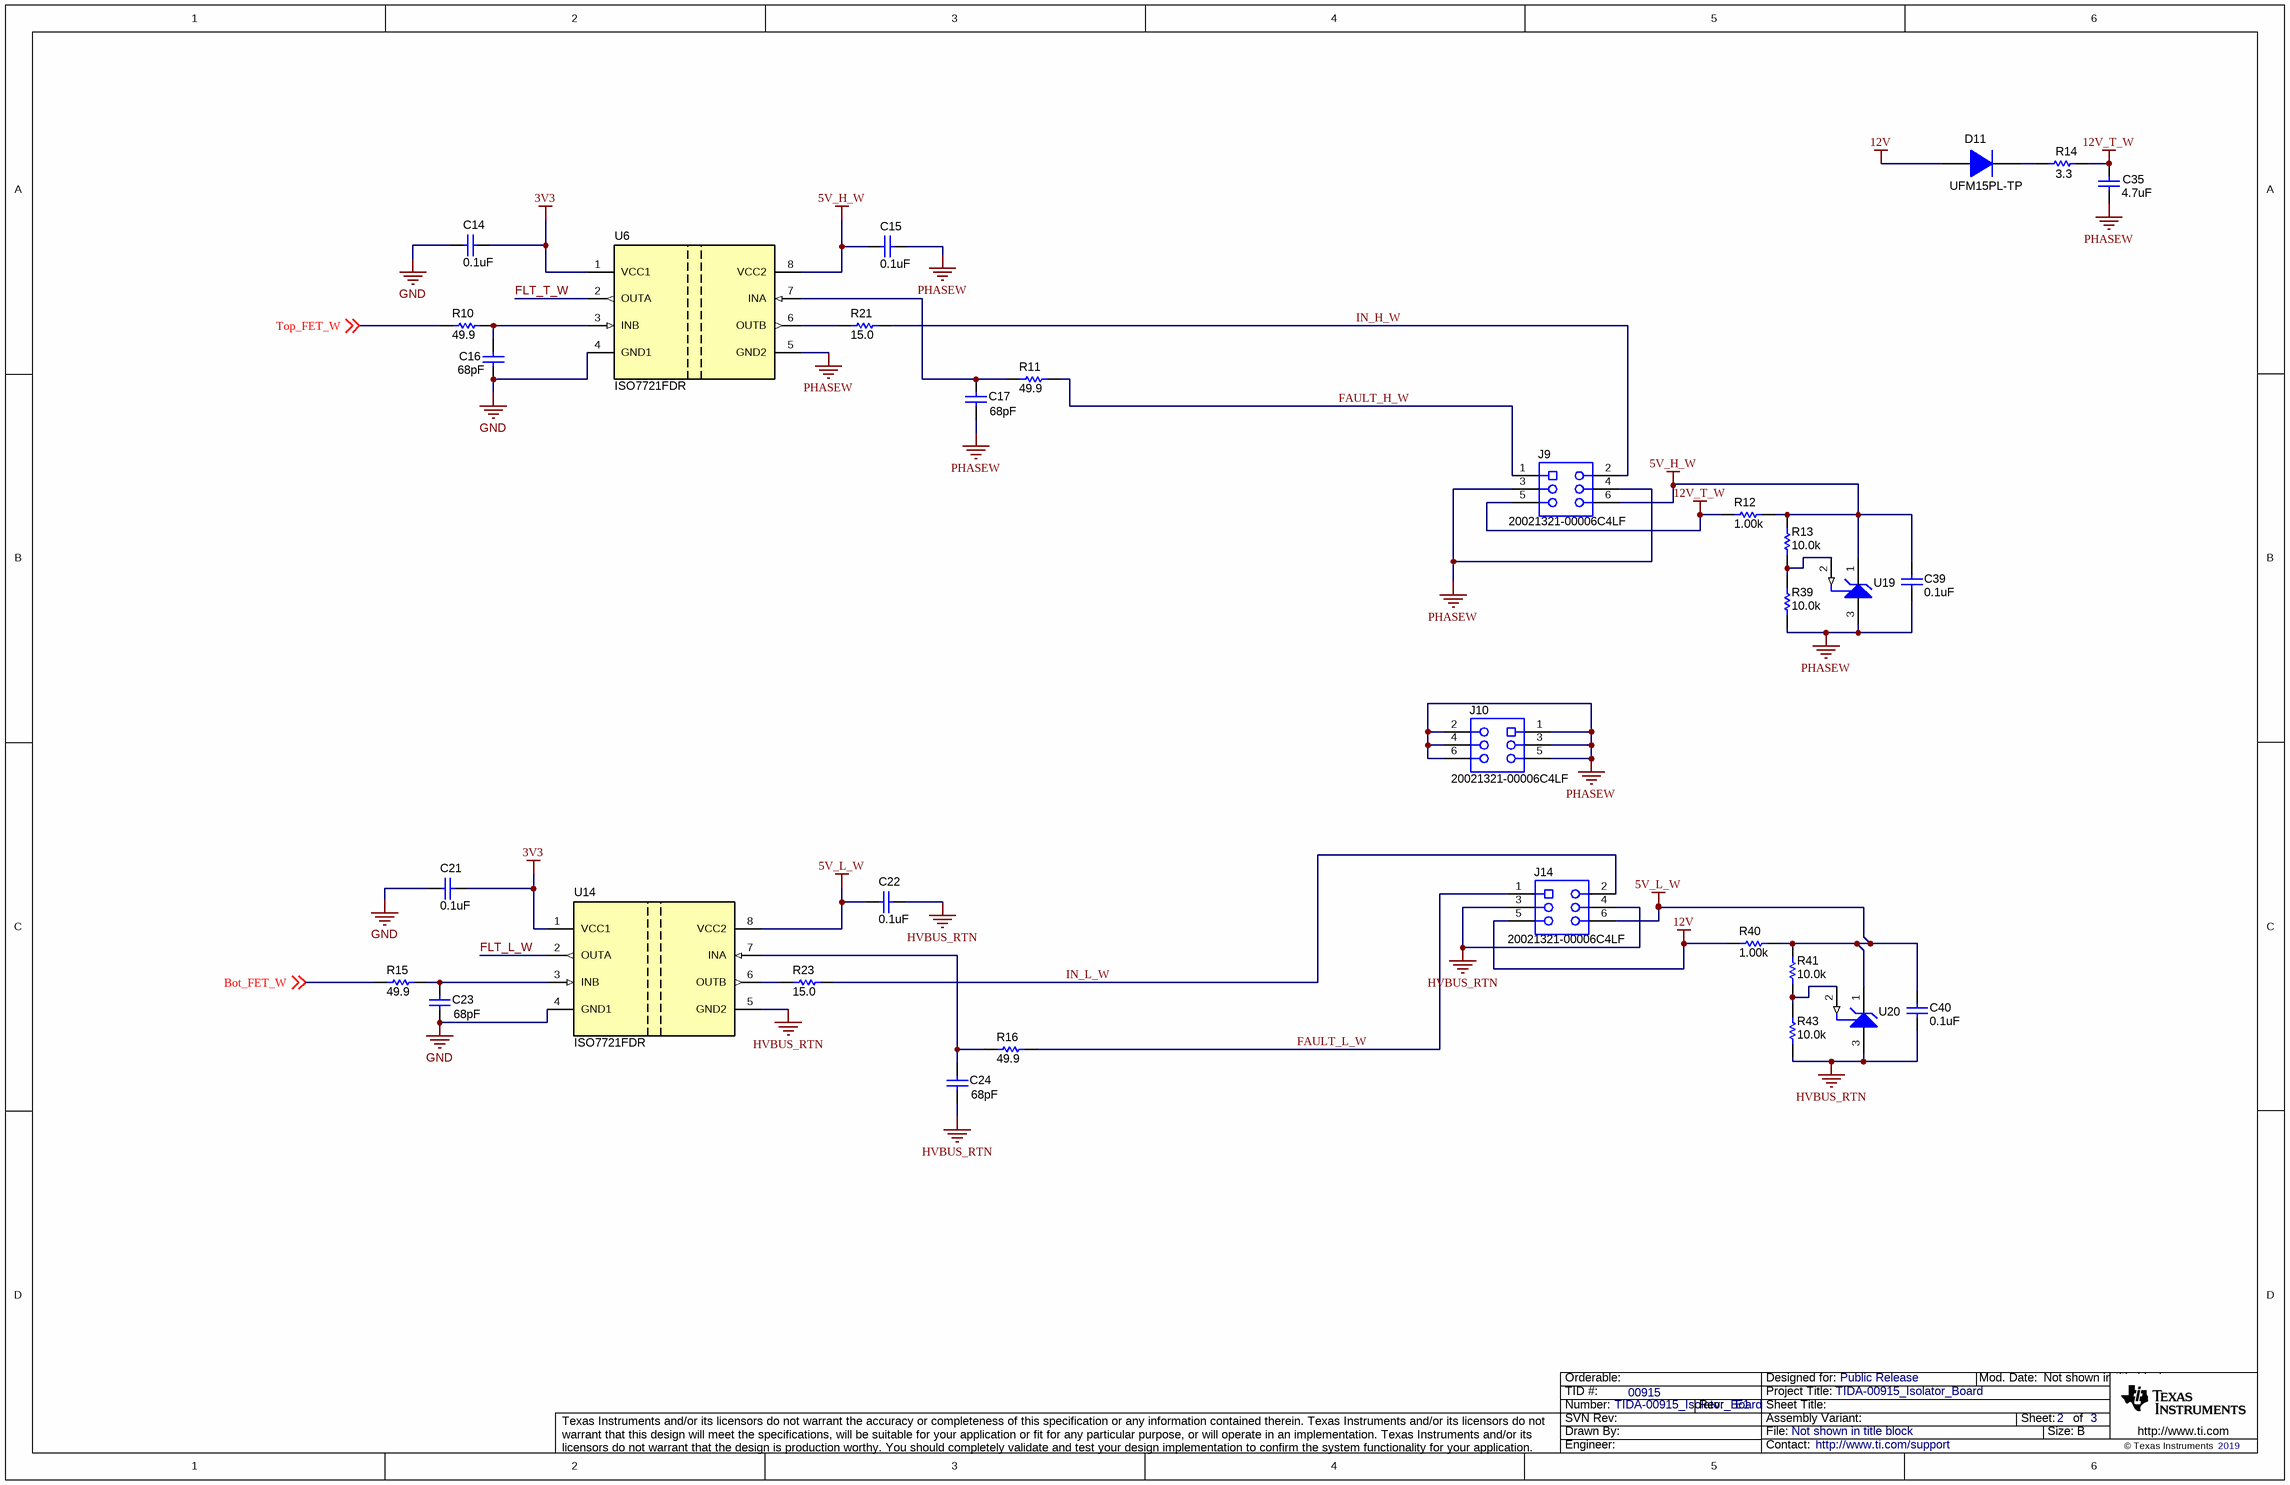
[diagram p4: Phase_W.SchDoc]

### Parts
C14  ValueDisplayed: 0.1uF  [0603]  (hidden comment: 06035C104KAT2A)
C15  ValueDisplayed: 0.1uF  [0603]  (hidden comment: 06035C104KAT2A)
C16  ValueDisplayed: 68pF  [0402]  (hidden comment: C1005C0G1H680J050BA)
C17  ValueDisplayed: 68pF  [0402]  (hidden comment: C1005C0G1H680J050BA)
C21  ValueDisplayed: 0.1uF  [0603]  (hidden comment: 06035C104KAT2A)
C22  ValueDisplayed: 0.1uF  [0603]  (hidden comment: 06035C104KAT2A)
C23  ValueDisplayed: 68pF  [0402]  (hidden comment: C1005C0G1H680J050BA)
C24  ValueDisplayed: 68pF  [0402]  (hidden comment: C1005C0G1H680J050BA)
C35  ValueDisplayed: 4.7uF  [0805_HV]  (hidden comment: C2012X7R1V475K125AC)
C39  ValueDisplayed: 0.1uF  [0603]  (hidden comment: 06035C104KAT2A)
C40  ValueDisplayed: 0.1uF  [0603]  (hidden comment: 06035C104KAT2A)
D11  UFM15PL-TP  [SOD-123FL]
J9  20021321-00006C4LF  [FCI_20021321-00006XXLF]
J10  20021321-00006C4LF  [FCI_20021321-00006XXLF]
J14  20021321-00006C4LF  [FCI_20021321-00006XXLF]
R10  ValueDisplayed: 49.9  [0603]  (hidden comment: RC0603FR-0749R9L)
R11  ValueDisplayed: 49.9  [0603]  (hidden comment: RC0603FR-0749R9L)
R12  ValueDisplayed: 1.00k  [0603]  (hidden comment: RC0603FR-071KL)
R13  ValueDisplayed: 10.0k  [0402]  (hidden comment: RC0402FR-0710KL)
R14  ValueDisplayed: 3.3  [0603]  (hidden comment: CRCW06033R30JNEA)
R15  ValueDisplayed: 49.9  [0603]  (hidden comment: RC0603FR-0749R9L)
R16  ValueDisplayed: 49.9  [0603]  (hidden comment: RC0603FR-0749R9L)
R21  ValueDisplayed: 15.0  [0603]  (hidden comment: RC0603FR-0715RL)
R23  ValueDisplayed: 15.0  [0603]  (hidden comment: RC0603FR-0715RL)
R39  ValueDisplayed: 10.0k  [0402]  (hidden comment: RC0402FR-0710KL)
R40  ValueDisplayed: 1.00k  [0603]  (hidden comment: RC0603FR-071KL)
R41  ValueDisplayed: 10.0k  [0402]  (hidden comment: RC0402FR-0710KL)
R43  ValueDisplayed: 10.0k  [0402]  (hidden comment: RC0402FR-0710KL)
U6  ISO7721FDR  [D0008B_HV]
U14  ISO7721FDR  [D0008B_HV]
U19  TL431ACDBZT  [DBZ0003A_N]  (value not drawn)
U20  TL431ACDBZT  [DBZ0003A_N]  (value not drawn)

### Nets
3V3: C14.2 C21.2 U6.1(VCC1) U14.1(VCC1)
5V_H_W: C15.1 C39.1 J9.6 R12.2 R13.2 U6.8(VCC2) U19.1(CATHODE)
5V_L_W: C22.1 C40.1 J14.6 R40.2 R41.2 U14.8(VCC2) U20.1(CATHODE)
12V: D11.2(A) J14.5 R40.1
12V_T_W: C35.1 J9.5 R12.1 R14.2
GND: C14.1 C16.2 C21.1 C23.2 U6.4(GND1) U14.4(GND1)
HVBUS_RTN: C22.2 C24.2 C40.2 J14.3 J14.4 R43.1 U14.5(GND2) U20.3(ANODE)
PHASEW: C15.2 C17.2 C35.2 C39.2 J9.3 J9.4 J10.1 J10.2 J10.3 J10.4 J10.5 J10.6 R39.1 U6.5(GND2) U19.3(ANODE)
Bot_FET_W: R15.1 ; off-sheet Bot_FET_W
FAULT_H_W: J9.1 R11.2
FAULT_L_W: J14.1 R16.2
FLT_L_W: U14.2(OUTA)
FLT_T_W: U6.2(OUTA)
IN_H_W: J9.2 R21.2
IN_L_W: J14.2 R23.2
Top_FET_W: R10.1 ; off-sheet Top_FET_W
NetC16_1: C16.1 R10.2 U6.3(INB)
NetC17_1: C17.1 R11.1 U6.7(INA)
NetC23_1: C23.1 R15.2 U14.3(INB)
NetC24_1: C24.1 R16.1 U14.7(INA)
NetD11_1: D11.1(K) R14.1
NetR13_1: R13.1 R39.2 U19.2(REF)
NetR21_1: R21.1 U6.6(OUTB)
NetR23_1: R23.1 U14.6(OUTB)
NetR41_1: R41.1 R43.2 U20.2(REF)

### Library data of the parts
C14 C15 C21 C22 C39 C40 = CMP-0006802-4: as C26 on sheet Phase_U
C16 C17 C23 C24 = CMP-0006251-2: as C45 on sheet Phase_U
C35 = CMP-0007885-2: as C32 on sheet Phase_U
D11 = CMP-0029148-2: as D4 on sheet Phase_U
J9 J10 J14 = CMP-0086011-1: as J3 on sheet Phase_U
R10 R11 R15 R16 = CMP-0023143-5: as R24 on sheet Phase_U
R12 R40 = CMP-0022895-5: as R1 on sheet Phase_U
R13 R39 R41 R43 = CMP-0078669-1: as R2 on sheet Phase_U
R14 = CMP-0025805-4: as R7 on sheet Phase_V
R21 R23 = CMP-0022819-4: as R17 on sheet Phase_U
U6 U14 = CMP-0085673-1: as U11 on sheet Phase_U
U19 U20 = CMP-0033071-1: as U15 on sheet Phase_U

## Sheet MCU_Interface.SchDoc
size 431 x 279 mm; Date: Not shown in title block; ApprovedBy: Not shown in title block; CheckedBy: Not shown in title block; Author: Not shown in title block; CompanyName: Not shown in title block; Engineer: Not shown in title block; Organization: Not shown in title block; Address1: Not shown in title block; Address2: Not shown in title block; Address3: Not shown in title block; Address4: Not shown in title block; DocumentNumber: 1; Revision: Use project parameter SCH_Rev; SheetNumber: 2; SheetTotal: 3; PageSetup: Record=PageOptions¦CenterHorizontal=True¦CenterVertical=True¦PrintScale=1.00¦XCorrection=1.00¦YCorrection=1.00¦PrintKind=0¦BorderSize=5000000¦LeftOffset=0¦BottomOffset=0¦Orientation=2¦PaperLength=1000¦PaperWidth=1000¦Scale=100¦PaperSource=15¦PrintQuality=600¦MediaType=1¦DitherType=10¦PaperKind=Letter¦PrintScaleMode=1
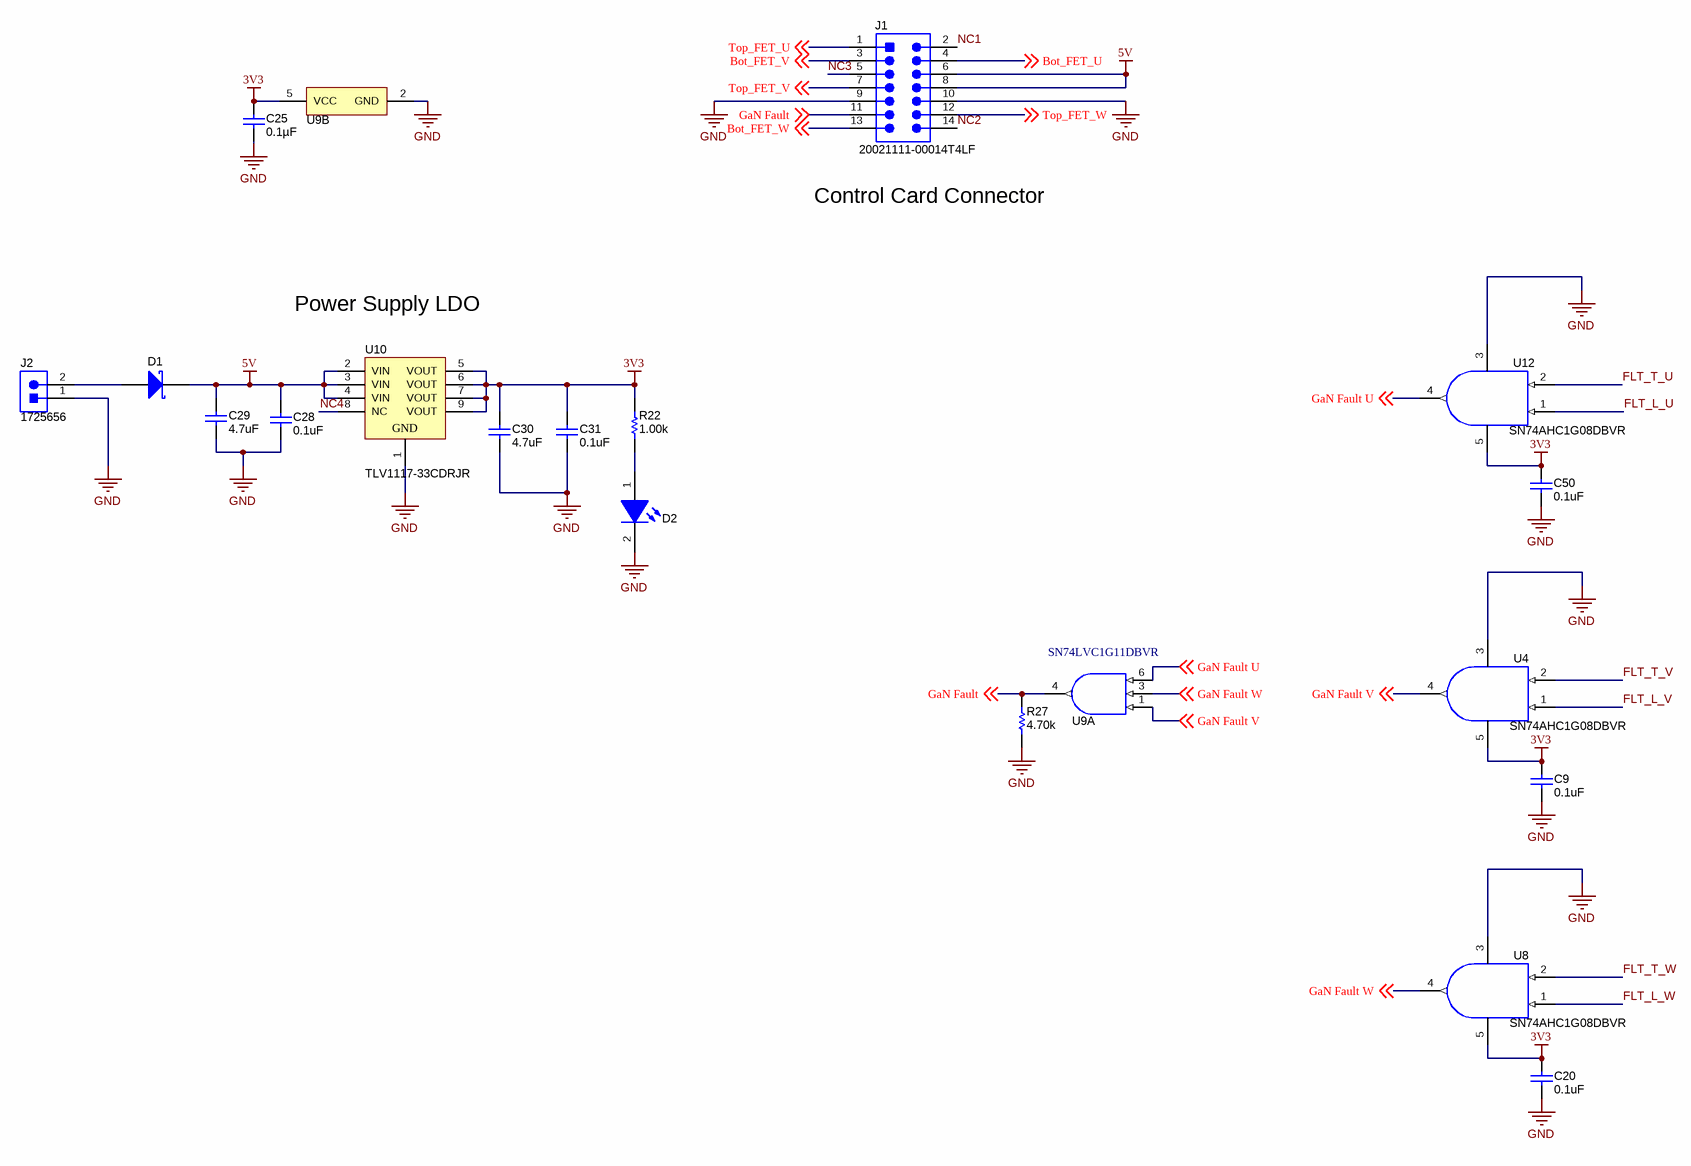
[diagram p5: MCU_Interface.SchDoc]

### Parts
C9  ValueDisplayed: 0.1uF  [0603]  (hidden comment: 06035C104KAT2A)
C20  ValueDisplayed: 0.1uF  [0603]  (hidden comment: 06035C104KAT2A)
C25  ValueDisplayed: 0.1µF  [0603]  (hidden comment: C1608X7R1H104K)
C28  ValueDisplayed: 0.1uF  [0603]  (hidden comment: 06035C104KAT2A)
C29  ValueDisplayed: 4.7uF  [0805_HV]  (hidden comment: C2012X7R1V475K125AC)
C30  ValueDisplayed: 4.7uF  [0805_HV]  (hidden comment: C2012X7R1V475K125AC)
C31  ValueDisplayed: 0.1uF  [0603]  (hidden comment: 06035C104KAT2A)
C50  ValueDisplayed: 0.1uF  [0603]  (hidden comment: 06035C104KAT2A)
D1  B1100-13-F  [SMA]  (value not drawn)
D2  LG L29K-G2J1-24-Z  [LG L29K_GREEN]  (value not drawn)
J1  20021111-00014T4LF  [FCI_20021111-00014T4LF]
J2  1725656  [CONN_1725656_1]
R22  ValueDisplayed: 1.00k  [0603]  (hidden comment: RT0603BRB071KL)
R27  ValueDisplayed: 4.70k  [0402]  (hidden comment: RC0402FR-074K7L)
U4  SN74AHC1G08DBVR  [DBV0005A_N]
U8  SN74AHC1G08DBVR  [DBV0005A_N]
U9  SN74LVC1G11DBVR  [DBV0006A_N]  (parts A,B of 2)
U10  TLV1117-33CDRJR  [DRJ0008A]
U12  SN74AHC1G08DBVR  [DBV0005A_N]

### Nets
3V3: C9.1 C20.1 C25.1 C30.2 C31.1 C50.1 R22.2 U4.5(V+) U8.5(V+) U9.5(VCC) U10.5(VOUT) U10.6(VOUT) U10.7(VOUT) U10.9(VOUT) U12.5(V+)
5V: C28.1 C29.2 D1.1(K) J1.6 J1.8 U10.2(VIN) U10.3(VIN) U10.4(VIN)
GND: C9.2 C20.2 C25.2 C28.2 C29.1 C30.1 C31.2 C50.2 D2.2(K) J1.9 J1.10 J2.1 R27.1 U4.3(V-) U8.3(V-) U9.2(GND) U10.1(GND) U12.3(V-)
Bot_FET_U: J1.4 ; off-sheet Bot_FET_U
Bot_FET_V: J1.3 ; off-sheet Bot_FET_V
Bot_FET_W: J1.13 ; off-sheet Bot_FET_W
FLT_L_U: U12.1(A)
FLT_L_V: U4.1(A)
FLT_L_W: U8.1(A)
FLT_T_U: U12.2(B)
FLT_T_V: U4.2(B)
FLT_T_W: U8.2(B)
GaN Fault: J1.11 R27.2 U9.4(Y) ; off-sheet GaN Fault
GaN Fault U: U9.6(C) U12.4(Y) ; off-sheet GaN Fault U
GaN Fault V: U4.4(Y) U9.1(A) ; off-sheet GaN Fault V
GaN Fault W: U8.4(Y) U9.3(B) ; off-sheet GaN Fault W
NC1: J1.2
NC2: J1.14
NC3: J1.5
NC4: U10.8(NC)
Top_FET_U: J1.1 ; off-sheet Top_FET_U
Top_FET_V: J1.7 ; off-sheet Top_FET_V
Top_FET_W: J1.12 ; off-sheet Top_FET_W
NetD1_2: D1.2(A) J2.2
NetD2_1: D2.1(A) R22.1

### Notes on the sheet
- Control Card Connector
- Power Supply LDO

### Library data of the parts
C9 C20 C28 C31 C50 = CMP-0006802-4: as C26 on sheet Phase_U
C25 = C1608X7R1H104K: CAP, CERM, 0.1 µF, 50 V, +/- 10%, X7R, 0603; Manufacturer: TDK; Polarized: N; CompType: Capacitor; Value: 0.1uF; U/M: EA; Cap_F: 0.0000001; Tolerance_%: 10; ESR_ohm: 0.017; Value1: 0.017 ohm; VDC_V: 50; Value2: 50V; TaMin_C: -55; TaMax_C: 125; AEC Category: Q200
C29 C30 = CMP-0007885-2: as C32 on sheet Phase_U
D1 = CMP-0028371-2: Diode, Schottky, 100 V, 1 A, SMA; Manufacturer: Diodes Inc.; Io_A: 1A; SizeZ_mm: 2.87; Green_REACh: Passed; TJmax_C: 150°C; Value: 100V; SizeAreaWB_mm2: 37.3428; Vf_V: 7.9dV; RJC_CperW: 25; SizeX_mm: 5.59; AEC Category: Q101; SizeArea_mm2: 16.3228; SizeY_mm: 2.92; Value2: 0.79V; Green_Lifecycle: Active
D2 = CMP-0002874-2: LED, Green, SMD; Manufacturer: OSRAM; Io_A: 2mA; Value2: 1.7V; Value1: W; Tjmax_C: 110°C
J1 = CMP-0081712-1: Header, 1.27mm, 7x2, Gold with Tin tail, TH; Manufacturer: FCI; Pitch_mm: 1.27; Gender: Male; Cert_UL: Y; Shrouded: N; Row_Count: 2
J2 = CMP-0055479-2: as J16 on sheet Phase_U
R22 = CMP-0023629-3: RES, 1.00 k, 0.1%, 0.1 W, 0603; Manufacturer: Yageo America; Power_W: 100mW; TempCo: 10 ppm/C; Value_Code: 1k00; U/M: EA; Value: 1.00k; EIA_Code: E192; Res_ohm: 1k; SizeX_mm: 1.6; SizeY_mm: 0.8; SizeZ_mm: 1; Value2: 0.1W; SizeArea_mm2: 1.28; AEC Qualified: N; VDC_V: 75V; AEC Category: Q200
R27 = CMP-0026739-1: RES, 4.70 k, 1%, 0.0625 W, 0402; Manufacturer: Yageo America; Power_W: 62.5mW; TempCo: 100 ppm/C; Value_Code: 4k70; U/M: EA; Value: 4.70k; Res_ohm: 4.7k; SizeX_mm: 1; SizeY_mm: 0.5; SizeZ_mm: 0.6; AEC Qualified: N; VDC_V: 50V; AEC Category: Q200
U4 U8 U12 = CMP-0051578-2: Single 2-Input Positive-AND Gate, DBV0005A (SOT-23-5); Manufacturer: Texas Instruments; Alternate PartNumber: SN74AHC1G08DBVT; Logic: True; Schmitt Trigger: No; Bits(#): 1; Voltage(Nom)(V): 3.3,5; F @ Nom Voltage(Max)(Mhz): 75; Output Type: CMOS; ICC @ Nom Voltage(Max)(mA): 0.01; Output Drive (IOL/IOH)(Max)(mA): 50/-50; VCC(Max)(V): 5.5; Technology Family: AHC; Gate Type: AND; Rating: Catalog; VCC(Min)(V): 2; tpd @ Nom Voltage(Max)(ns): 12.3,7.9; AEC Category: Q200; AEC Qualified: N; CompType: IC; SizeAreaWB_mm2: 14.82; SizeArea_mm2: 8.12; SizeX_mm: 2.8; SizeY_mm: 2.9; SizeZ_mm: 1.45
U9 = CMP-0051219-1: Single 3-Input Positive-AND Gate, DBV0006A, LARGE T&R; Manufacturer: Texas Instruments; Output Type: CMOS; Voltage(Nom)(V): 1.8,2.5,3.3,5; ICC @ Nom Voltage(Max)(mA): 0.01; VCC(Min)(V): 1.65; Output Drive (IOL/IOH)(Max)(mA): 32/-32; Schmitt Trigger: No; Input Type: CMOS/TTL; VCC(Max)(V): 5.5; Gate Type: AND; Rating: Catalog; tpd @ Nom Voltage(Max)(ns): 20,7.8,6.2,4.6; Bits(#): 1; F @ Nom Voltage(Max)(Mhz): 150; Logic: True; Technology Family: LVC
U10 = CMP-0037130-1: LDO with 4.7 to 15 V Input and 3.3 V Output, 0 to 125 degC, 8-Pin SON (DRJ), Green (RoHS & no Sb/Br); Manufacturer: Texas Instruments; Vin(Max)(V): 15; Vout(Min)(V): 3.3; Vin(Min)(V): 4.7; SubFamily: Single Channel LDO; Iout(Max)(A): 0.8; Iq(Typ)(mA): 5

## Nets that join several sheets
3V3: Phase_U (C36.2 C53.2 U11.1 U13.1), Phase_V (C3.2 C10.2 U2.1 U5.1), Phase_W (C14.2 C21.2 U6.1 U14.1), MCU_Interface (15 pins)
12V: Phase_U (D4.2 J12.5 J16.2 R1.1), Phase_V (D8.2 J13.5 R35.1), Phase_W (D11.2 J14.5 R40.1)
GND: Phase_U (6 pins), Phase_V (6 pins), Phase_W (6 pins), MCU_Interface (18 pins)
HVBUS_RTN: Phase_U (16 pins), Phase_V (8 pins), Phase_W (8 pins)
PHASEV: Phase_U (J15.2), Phase_V (15 pins)
PHASEW: Phase_U (J15.3), Phase_W (15 pins)
Bot_FET_U: Phase_U (R31.1), MCU_Interface (J1.4)
Bot_FET_V: Phase_V (R8.1), MCU_Interface (J1.3)
Bot_FET_W: Phase_W (R15.1), MCU_Interface (J1.13)
FLT_L_U: Phase_U (U13.2), MCU_Interface (U12.1)
FLT_L_V: Phase_V (U5.2), MCU_Interface (U4.1)
FLT_L_W: Phase_W (U14.2), MCU_Interface (U8.1)
FLT_T_U: Phase_U (U11.2), MCU_Interface (U12.2)
FLT_T_V: Phase_V (U2.2), MCU_Interface (U4.2)
FLT_T_W: Phase_W (U6.2), MCU_Interface (U8.2)
Top_FET_U: Phase_U (R24.1), MCU_Interface (J1.1)
Top_FET_V: Phase_V (R3.1), MCU_Interface (J1.7)
Top_FET_W: Phase_W (R10.1), MCU_Interface (J1.12)

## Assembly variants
001: not fitted FID1 FID2 FID3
